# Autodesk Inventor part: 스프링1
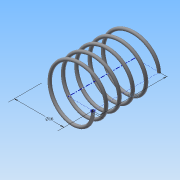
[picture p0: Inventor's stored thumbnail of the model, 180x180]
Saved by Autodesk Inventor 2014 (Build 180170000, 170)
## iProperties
Created: 2015-06
Part Number: 스프링1
Material: 강철, 연강
Document SubType Name: Modeling
Designer: MYHOME
Density: 1 g/cm^3
Appearance: 강철
Author: MYHOME
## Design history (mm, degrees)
sketch "스케치1"
  geometry: L1 (0, 0)-(8, 0); L2 (8, 0)-(8, 21.5); L3 (8, 21.5)-(0, 21.5); L4 (0, 21.5)-(0, 0); C1 r 0.5 at (8, 0)
  constraints: 8 end point, 2 parallel, 1 centre point, 1 coincident, 1 horizontal, 1 perpendicular
  dimensions: "d0" = 16 diameter of L2 L4; "d1" = 21.5 distance of L1.end L2.end (derived); "d2" = 1 diameter of C1
feature "코일2" sketch "스케치1" pitch "d17" = 10; turns "d19" = 5; dims "d18" = 21.5 (= d1), "d20" = 0, angle "d21" = 90 deg, angle "d22" = 90 deg, "d23" = 0, "d24" = 0
node "작업 평면3"
sketch "스케치4"
  geometry: L1 (-8.5, 0)-(-7.5, 0) reference; 1 further point
  constraints: 1 horizontal alignment
extrude "돌출3" cut sketch "스케치4" stored distance "d26" = 10; taper "d27" = 0 deg
node "작업 평면4"
sketch "스케치5"
  geometry: L1 (-7.5, 0)-(-8.5, 0) reference; 1 further point
  constraints: 1 horizontal alignment
extrude "돌출4" cut sketch "스케치5" stored distance "d29" = 10; taper "d30" = 0 deg
node "솔리드2"
node "절단 모서리 투영3"
node "절단 모서리 투영4"
other parameters: "d25" = 0, "d28" = 21.5 (= d1)
